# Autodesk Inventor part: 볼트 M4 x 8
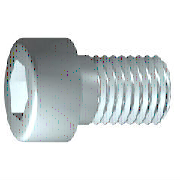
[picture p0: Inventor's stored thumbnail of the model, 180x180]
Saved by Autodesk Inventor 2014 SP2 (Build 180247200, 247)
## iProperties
IsCustomPart: 0
Created: 2012-02
Part Number: 볼트 M4 x 8
Material: 스테인리스강
Description: 6각 소켓 머리 캡 나사
Document SubType Name: Modeling
Standard: ISO 4762
Designer: mduedu
Standard Revision: Fourth edition 2004-03-01
Standards Organization: ISO
Language: ko-KR
Size Designation: M4 x 8
Categories: <MemberInstance><Categories><Category DisplayName="조임쇠" InternalName="e4da775c-781d-43d5-af7c-5136215cf5a6" Mnemonic="FSTN"><Category DisplayName="볼트" InternalN
Density: 8.08 g/cm^3
Appearance: 반광택
Mass: 1.89105 g
Surface Area: 2.80587 cm^2
Volume: 0.234041 cm^3
Author: mduedu
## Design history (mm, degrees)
sketch "스케치1"
  geometry: L1 (-1, 0)-(8, 0); L2 (8, 0)-(8, 2); L3 (8, 2)-(1.75, 2); L4 (1.75, 2)-(1.32, 2); L5 (1.32, 2)-(0, 2); L6 (0, 2)-(0, 3.5); L7 (0, 3.5)-(-4, 3.5); L8 (-4, 3.5)-(-4, 1.732); L9 (-4, 1.732)-(-2, 1.732); L10 (-2, 1.732)-(-1, 0); L11 (-6.4, 0)-(10.4, 0) reference; L12 (0, -0.7)-(0, 4.2) reference; L13 (1.75, 2)-(0, 2)
  constraints: 22 end point, 6 parallel, 2 collinear, 2 perpendicular, 1 horizontal, 1 point on line
  dimensions: "d1" = 6.25 distance from line of L3.end L2 (= GEL); "d2" = 0.42952 distance of L4.end L3.end (computed from GAL); "d3" = 4 distance between parallel lines of L8 L6 (= KOH); "d4" = 2 distance of L8.end L9.end (= INTI); "d5" = 60 deg angle of L10 L1; "d6" = 4 diameter of L3 L1 (= GD); "d7" = 4 diameter of L5 L1 (= BDM); "d8" = 3.4641 diameter of L9 L1 (= 1.1547 x SW); "d9" = 7 diameter of L7 L1 (= KOD); "d26" = 8 distance between parallel lines of L12 L2 (= NLG)
revolve "본체" sketch "스케치1" stored, may be unused: angle "d10" = 90 deg
sketch "스케치2"
  geometry: L1 (0, -4.9)-(0, 4.9) reference; L2 (-4.9, 0)-(4.9, 0) reference; L3 (1.732, 0)-(0.866, -1.5); L4 (0.866, -1.5)-(-0.866, -1.5); L5 (-0.866, -1.5)-(-1.732, 0); L6 (-1.732, 0)-(-0.866, 1.5); L7 (-0.866, 1.5)-(0.866, 1.5); L8 (0.866, 1.5)-(1.732, 0); 2 further points
  constraints: 12 end point, 1 coincident, 1 horizontal alignment, 1 point on line, 12 other
extrude "슬롯" join sketch "스케치2" stored distance "d11" = 10; taper "d12" = 0 deg
workplane "Work Plane1"
fillet "Fillet2" dims "d30" = 0.1 (= R)
body "Solid1"
fillet "모깎기1" dims "d17" = 0.4 (= RR)
feature "스레드" dims "d13" = 6.25 (= GEL), "d14" = 0
chamfer "모따기1" distance "d15" = 0.42941 (= -0.5 x SPD + 0.5 x GD); stored, may be unused: second distance "d16" = 0.42941 (= GUL), angle "d27" = 45 deg
other parameters: "GD" = 4 [user parameter; used in 2 equation terms], "NLG" = 8 [user parameter; used in 1 equation term], "GEL" = 6.25 [user parameter; used in 2 equation terms], "KOD" = 7 [user parameter; used in 1 equation term], "KOH" = 4 [user parameter; used in 1 equation term], "INTI" = 2 [user parameter; used in 1 equation term], "GAL" = 0.42941 (= 0.61345 x PTC) [user parameter; used in 1 equation term], "GUL" = 0.42941 (= 0.61345 x PTC) [user parameter; used in 1 equation term], "BDM" = 4 (= NND) [user parameter; used in 1 equation term], "SW" = 3 [user parameter; used in 2 equation terms], "RR" = 0.4 [user parameter; used in 1 equation term], "SPD" = 3.14117 (= NND - 1.2269 x PTC) [user parameter; used in 1 equation term], "d19" = 0, "d28" = 0, "d29" = 0, "R" = 0.1 [user parameter; used in 1 equation term], "TOA" = 30 deg [user parameter], "GD1" = 3.14117 (= THREADDIA - 1.2269 x PTC) [user parameter], "THREADDIA" = 4 [user parameter; used in 1 equation term], "FAWI" = 45 deg [user parameter], "TPU" = 14.28571 (computed from PTC) [user parameter], "PTC" = 0.7 [user parameter; used in 5 equation terms], "NND" = 4 [user parameter; used in 2 equation terms], "E0" = 3.465 (= 1.155 x SW) [user parameter]
